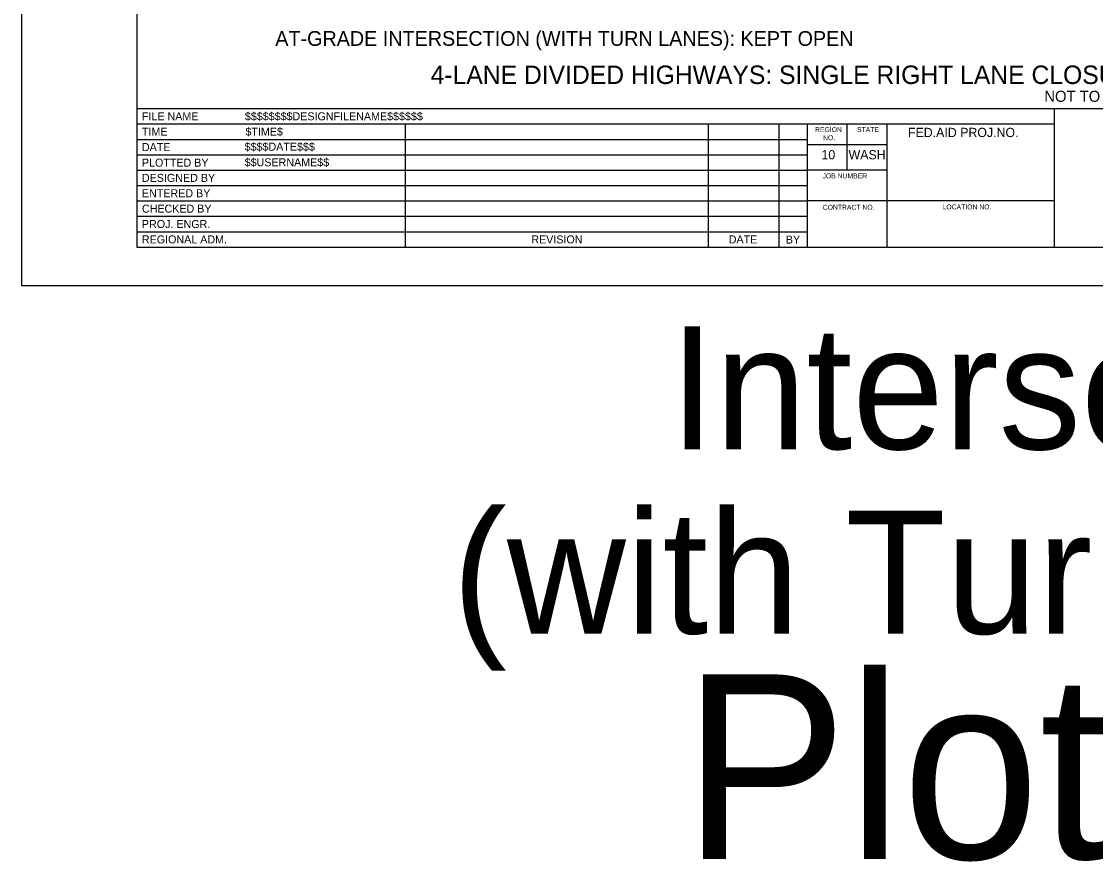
# Model space of a CAD drawing. Extents: x 99958 to 100136, y 99935 to 100013.
# Drawn here: x 100059.06 to 100067.79, y 99965.01 to 99971.83 of the extents above; entities that cross this region are included whole.
import ezdxf

# ---------------------------------------------------------------- set-up
doc = ezdxf.new("R2010")
doc.units = 0
for name, color, linetype in [('SH_DE_DetailHeading1Text', 7, 'Continuous'), ('SH_DE_DetailHeading2Text', 7, 'Continuous'), ('SH_GI_PlotLimits', 7, 'Continuous'), ('SH_GI_SheetBorder', 7, 'Continuous'), ('SH_GI_SheetLocationText', 7, 'Continuous'), ('SH_GI_SheetTextInCells', 7, 'Continuous'), ('SH_GI_TitleBlockText', 7, 'Continuous')]:
    doc.layers.add(name, color=color, linetype=linetype)

msp = doc.modelspace()

# ---------------------------------------------------------------- linework, layer by layer
at = {"layer": 'SH_GI_PlotLimits'}
msp.add_lwpolyline([(100059.0625, 99969.6875), (100076.0625, 99969.6875), (100076.0625, 99980.6875), (100059.0625, 99980.6875)], close=True, dxfattribs=at)
at = {"layer": 'SH_GI_SheetBorder'}
for p, q in [((100060, 99980.375), (100060, 99970)), ((100060, 99971.1259), (100075.75, 99971.1259)), ((100067.4566, 99970), (100067.4566, 99971.1259)), ((100060, 99971.0008), (100067.4566, 99971.0008)), ((100062.179, 99971.0008), (100062.179, 99970)), ((100064.641, 99971.0008), (100064.641, 99970)), ((100065.2164, 99971.0008), (100065.2164, 99970)), ((100065.4451, 99971.0008), (100065.4451, 99970)), ((100065.7719, 99970.6255), (100065.7719, 99971.0008)), ((100066.0956, 99970), (100066.0956, 99971.0008)), ((100060, 99970.8757), (100062.1821, 99970.8757)), ((100062.1821, 99970.8757), (100065.4466, 99970.8757)), ((100066.0958, 99970.831), (100065.4466, 99970.831)), ((100060, 99970.7506), (100062.1821, 99970.7506)), ((100062.1821, 99970.7506), (100065.4466, 99970.7506)), ((100060, 99970.6255), (100065.4466, 99970.6255)), ((100066.0958, 99970.6255), (100065.4466, 99970.6255)), ((100060, 99970.5004), (100065.4466, 99970.5004)), ((100060, 99970.3753), (100065.4466, 99970.3753)), ((100067.4566, 99970.3753), (100065.4466, 99970.3753)), ((100060, 99970.2502), (100065.4466, 99970.2502)), ((100060, 99970.1251), (100065.4466, 99970.1251)), ((100060, 99970), (100075.75, 99970))]:
    msp.add_line(p, q, dxfattribs=at)

# ---------------------------------------------------------------- texts
at = {"layer": 'SH_DE_DetailHeading1Text'}
for s, height, p in [('4-LANE DIVIDED HIGHWAYS: SINGLE RIGHT LANE CLOSURE (45+ MPH, MAINTAIN EXISTING SPEED LIMIT)', 0.15, (100062.3867, 99971.3259)), ('NOT TO SCALE', 0.09, (100067.3727, 99971.1809))]:
    msp.add_text(s, height=height, rotation=360, dxfattribs=at).set_placement(p)
at = {"layer": 'SH_DE_DetailHeading2Text'}
msp.add_text('AT-GRADE INTERSECTION (WITH TURN LANES): KEPT OPEN', height=0.12, rotation=360, dxfattribs=at).set_placement((100061.1244, 99971.6359))
at = {"layer": 'SH_GI_SheetLocationText'}
for s, height, p in [('Intersections', 1, (100064.3261, 99968.3571)), ('(with Turns Lanes)', 1, (100062.5618, 99966.8571)), ('Plot 14', 1.5, (100064.4341, 99965.0267))]:
    msp.add_text(s, height=height, dxfattribs=at).set_placement(p)
at = {"layer": 'SH_GI_SheetTextInCells'}
for s, height, p in [('FILE NAME', 0.06505, (100060.041, 99971.0308)), ('TIME', 0.06505, (100060.041, 99970.9057)), ('REGION', 0.04003, (100065.5099, 99970.9352)), ('NO.', 0.04003, (100065.5752, 99970.869)), ('STATE', 0.04003, (100065.8511, 99970.9357)), ('FED.AID PROJ.NO.', 0.07506, (100066.2652, 99970.8945)), ('DATE', 0.06505, (100060.041, 99970.7806)), ('PLOTTED BY', 0.06505, (100060.041, 99970.6538)), ('10', 0.07506, (100065.5621, 99970.7131)), ('WASH', 0.07506, (100065.7826, 99970.7131)), ('DESIGNED BY', 0.065052, (100060.041, 99970.5304)), ('JOB NUMBER', 0.04003, (100065.5712, 99970.5587)), ('ENTERED BY', 0.06505, (100060.041, 99970.4053)), ('CHECKED BY', 0.06505, (100060.041, 99970.2802)), ('CONTRACT NO.', 0.040032, (100065.5725, 99970.3037)), ('LOCATION NO.', 0.040032, (100066.5465, 99970.3067)), ('PROJ. ENGR.', 0.065052, (100060.041, 99970.1551)), ('REGIONAL ADM.', 0.065052, (100060.041, 99970.03)), ('REVISION', 0.06505, (100063.2048, 99970.03)), ('DATE', 0.06505, (100064.8091, 99970.03)), ('BY', 0.06505, (100065.2725, 99970.0285))]:
    msp.add_text(s, height=height, dxfattribs=at).set_placement(p)
at = {"layer": 'SH_GI_TitleBlockText'}
for s, height, p in [('$$$$$$$$DESIGNFILENAME$$$$$$', 0.065052, (100060.8775, 99971.0308)), ('$TIME$', 0.06505, (100060.882, 99970.9059)), ('$$$$DATE$$$', 0.065052, (100060.8759, 99970.7835)), ('$$USERNAME$$', 0.065052, (100060.8759, 99970.6567))]:
    msp.add_text(s, height=height, dxfattribs=at).set_placement(p)

doc.saveas('drawing.dxf')
